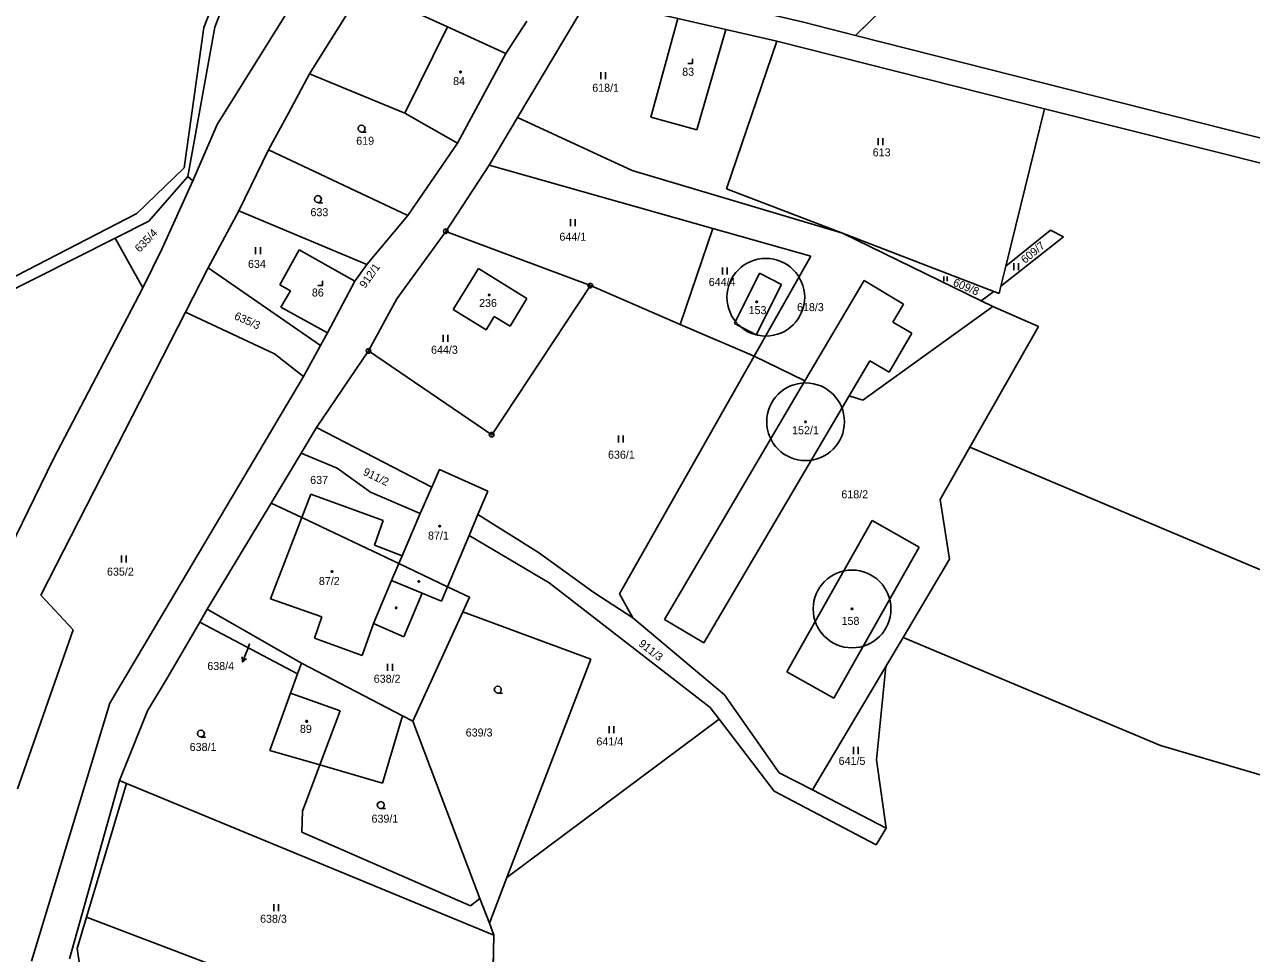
# Model space of a CAD drawing. Extents: x -580551 to -575069, y -1073031 to -1067931.
# Drawn here: x -578344.9 to -578084.3, y -1070721.5 to -1070524.1 of the extents above; entities that cross this region are included whole.
import ezdxf

# ---------------------------------------------------------------- set-up
doc = ezdxf.new("R2010")
doc.units = 0
for name, color, linetype in [('Druh pozemku', 7, 'Continuous'), ('Geodetické body', 7, 'Continuous'), ('Katastrální hranice', 7, 'Continuous'), ('Parcela', 7, 'Continuous'), ('Parcelní číslo', 7, 'Continuous'), ('Parcelní číslo_stavba', 7, 'Continuous'), ('Pomocná vrstva', 7, 'Continuous'), ('SR - hranice státu', 7, 'Continuous'), ('stavební parcely', 7, 'Continuous'), ('Vnitřní kresba', 7, 'Continuous'), ('Vrstva 6', 7, 'Continuous')]:
    doc.layers.add(name, color=color, linetype=linetype)

msp = doc.modelspace()

# ---------------------------------------------------------------- linework, layer by layer
at = {"layer": 'Druh pozemku'}
for p, q in [((-578222.49, -1070534.2), (-578222.49, -1070535.7)), ((-578221.49, -1070535.7), (-578221.49, -1070534.2)), ((-578163.6, -1070548.24), (-578163.6, -1070549.74)), ((-578162.6, -1070549.74), (-578162.6, -1070548.24)), ((-578228.97, -1070565.44), (-578228.97, -1070566.94)), ((-578227.97, -1070566.94), (-578227.97, -1070565.44)), ((-578295.84, -1070571.39), (-578295.84, -1070572.89)), ((-578294.84, -1070572.89), (-578294.84, -1070571.39)), ((-578196.63, -1070575.72), (-578196.63, -1070577.22)), ((-578195.63, -1070577.22), (-578195.63, -1070575.72)), ((-578134.79, -1070574.83), (-578134.79, -1070576.33)), ((-578133.79, -1070576.33), (-578133.79, -1070574.83)), ((-578149.625, -1070577.655), (-578149.625, -1070578.66)), ((-578148.955, -1070578.66), (-578148.955, -1070577.655)), ((-578256.01, -1070590.05), (-578256.01, -1070591.55)), ((-578255.01, -1070591.55), (-578255.01, -1070590.05)), ((-578218.76, -1070611.41), (-578218.76, -1070612.91)), ((-578217.76, -1070612.91), (-578217.76, -1070611.41)), ((-578324.34, -1070636.9), (-578324.34, -1070638.4)), ((-578323.34, -1070638.4), (-578323.34, -1070636.9)), ((-578267.79, -1070659.94), (-578267.79, -1070661.44)), ((-578266.79, -1070661.44), (-578266.79, -1070659.94)), ((-578220.74, -1070673.15), (-578220.74, -1070674.65)), ((-578219.74, -1070674.65), (-578219.74, -1070673.15)), ((-578168.82, -1070677.59), (-578168.82, -1070679.09)), ((-578167.82, -1070679.09), (-578167.82, -1070677.59)), ((-578291.97, -1070710.98), (-578291.97, -1070712.48)), ((-578290.97, -1070712.48), (-578290.97, -1070710.98))]:
    msp.add_line(p, q, dxfattribs=at)
for points in [[(-578204.03, -1070532.41), (-578203.03, -1070532.41), (-578203.03, -1070531.41)], [(-578273.33, -1070546.96), (-578273.71, -1070546.86), (-578273.98, -1070546.59), (-578274.08, -1070546.22), (-578273.98, -1070545.85), (-578273.71, -1070545.58), (-578273.34, -1070545.48), (-578272.97, -1070545.58), (-578272.7, -1070545.85), (-578272.6, -1070546.23), (-578272.7, -1070546.61), (-578272.97, -1070546.88), (-578273.35, -1070546.98), (-578272.35, -1070546.98)], [(-578282.59, -1070561.95), (-578282.97, -1070561.85), (-578283.24, -1070561.58), (-578283.34, -1070561.21), (-578283.24, -1070560.84), (-578282.97, -1070560.57), (-578282.6, -1070560.47), (-578282.23, -1070560.57), (-578281.96, -1070560.84), (-578281.86, -1070561.22), (-578281.96, -1070561.6), (-578282.23, -1070561.87), (-578282.61, -1070561.97), (-578281.61, -1070561.97)], [(-578282.63, -1070579.53), (-578281.63, -1070579.53), (-578281.63, -1070578.53)], [(-578244.38, -1070666.14), (-578244.76, -1070666.04), (-578245.03, -1070665.77), (-578245.13, -1070665.4), (-578245.03, -1070665.03), (-578244.76, -1070664.76), (-578244.39, -1070664.66), (-578244.02, -1070664.76), (-578243.75, -1070665.03), (-578243.65, -1070665.41), (-578243.75, -1070665.79), (-578244.02, -1070666.06), (-578244.4, -1070666.16), (-578243.4, -1070666.16)], [(-578307.46, -1070675.47), (-578307.84, -1070675.37), (-578308.11, -1070675.1), (-578308.21, -1070674.73), (-578308.11, -1070674.36), (-578307.84, -1070674.09), (-578307.47, -1070673.99), (-578307.1, -1070674.09), (-578306.83, -1070674.36), (-578306.73, -1070674.74), (-578306.83, -1070675.12), (-578307.1, -1070675.39), (-578307.48, -1070675.49), (-578306.48, -1070675.49)], [(-578269.24, -1070690.67), (-578269.62, -1070690.57), (-578269.89, -1070690.3), (-578269.99, -1070689.93), (-578269.89, -1070689.56), (-578269.62, -1070689.29), (-578269.25, -1070689.19), (-578268.88, -1070689.29), (-578268.61, -1070689.56), (-578268.51, -1070689.94), (-578268.61, -1070690.32), (-578268.88, -1070690.59), (-578269.26, -1070690.69), (-578268.26, -1070690.69)]]:
    msp.add_lwpolyline(points, dxfattribs=at)
for points in [[(-578252.21, -1070534.05), (-578252.12, -1070534.2), (-578252.21, -1070534.35), (-578252.39, -1070534.35), (-578252.48, -1070534.2), (-578252.39, -1070534.05)], [(-578246.14, -1070581.41), (-578246.05, -1070581.56), (-578246.14, -1070581.71), (-578246.32, -1070581.71), (-578246.41, -1070581.56), (-578246.32, -1070581.41)], [(-578189.29, -1070582.89), (-578189.2, -1070583.04), (-578189.29, -1070583.19), (-578189.47, -1070583.19), (-578189.56, -1070583.04), (-578189.47, -1070582.89)], [(-578178.92, -1070608.36), (-578178.83, -1070608.51), (-578178.92, -1070608.66), (-578179.1, -1070608.66), (-578179.19, -1070608.51), (-578179.1, -1070608.36)], [(-578256.64, -1070630.51), (-578256.55, -1070630.66), (-578256.64, -1070630.81), (-578256.82, -1070630.81), (-578256.91, -1070630.66), (-578256.82, -1070630.51)], [(-578279.53, -1070640.17), (-578279.44, -1070640.32), (-578279.53, -1070640.47), (-578279.71, -1070640.47), (-578279.8, -1070640.32), (-578279.71, -1070640.17)], [(-578261.09, -1070642.28), (-578261, -1070642.43), (-578261.09, -1070642.58), (-578261.27, -1070642.58), (-578261.36, -1070642.43), (-578261.27, -1070642.28)], [(-578265.88, -1070647.89), (-578265.79, -1070648.04), (-578265.88, -1070648.19), (-578266.06, -1070648.19), (-578266.15, -1070648.04), (-578266.06, -1070647.89)], [(-578169.04, -1070648.12), (-578168.95, -1070648.27), (-578169.04, -1070648.42), (-578169.22, -1070648.42), (-578169.31, -1070648.27), (-578169.22, -1070648.12)], [(-578284.89, -1070671.99), (-578284.8, -1070672.14), (-578284.89, -1070672.29), (-578285.07, -1070672.29), (-578285.16, -1070672.14), (-578285.07, -1070671.99)]]:
    msp.add_lwpolyline(points, close=True, dxfattribs=at)
at = {"layer": 'Geodetické body'}
for p, q in [((-578255.57, -1070568.05), (-578255.33, -1070568.05)), ((-578224.84, -1070579.59), (-578224.6, -1070579.59)), ((-578271.97, -1070593.46), (-578271.73, -1070593.46)), ((-578245.81, -1070611.28), (-578245.57, -1070611.28))]:
    msp.add_line(p, q, dxfattribs=at)
for points in [[(-578255.3, -1070567.57), (-578255.05, -1070567.75), (-578254.95, -1070568.04), (-578255.05, -1070568.33), (-578255.3, -1070568.51), (-578255.61, -1070568.51), (-578255.86, -1070568.33), (-578255.96, -1070568.04), (-578255.86, -1070567.75), (-578255.61, -1070567.57)], [(-578224.57, -1070579.11), (-578224.32, -1070579.29), (-578224.22, -1070579.58), (-578224.32, -1070579.87), (-578224.57, -1070580.05), (-578224.88, -1070580.05), (-578225.13, -1070579.87), (-578225.23, -1070579.58), (-578225.13, -1070579.29), (-578224.88, -1070579.11)], [(-578271.7, -1070592.98), (-578271.45, -1070593.16), (-578271.35, -1070593.45), (-578271.45, -1070593.74), (-578271.7, -1070593.92), (-578272.01, -1070593.92), (-578272.26, -1070593.74), (-578272.36, -1070593.45), (-578272.26, -1070593.16), (-578272.01, -1070592.98)], [(-578245.54, -1070610.8), (-578245.29, -1070610.98), (-578245.19, -1070611.27), (-578245.29, -1070611.56), (-578245.54, -1070611.74), (-578245.85, -1070611.74), (-578246.1, -1070611.56), (-578246.2, -1070611.27), (-578246.1, -1070610.98), (-578245.85, -1070610.8)]]:
    msp.add_lwpolyline(points, close=True, dxfattribs=at)
at = {"layer": 'Katastrální hranice'}
for p, q in [((-578306.85, -1070524.72), (-578294.73, -1070494.02)), ((-578311.04, -1070554.58), (-578306.85, -1070524.72)), ((-578321.11, -1070564.23), (-578311.04, -1070554.58)), ((-578356.67, -1070582.67), (-578321.11, -1070564.23))]:
    msp.add_line(p, q, dxfattribs=at)
at = {"layer": 'Parcela'}
for p, q in [((-578168.38, -1070526.44), (-578127.99, -1070486.75)), ((-578294.71, -1070498.96), (-578304.49, -1070524.64)), ((-578282.8, -1070511.36), (-578304.04, -1070545.35)), ((-578284.43, -1070534.61), (-578272.99, -1070516.43)), ((-578225.1, -1070518.49), (-578240.19, -1070543.87)), ((-578238.22, -1070523.39), (-578242.66, -1070530.27)), ((-578206.11, -1070522.84), (-578211.9, -1070543.82)), ((-578206.11, -1070522.84), (-578195.97, -1070525.17)), ((-578168.38, -1070526.44), (-578179.44, -1070523.64)), ((-578304.49, -1070524.64), (-578310.24, -1070556.41)), ((-578202.12, -1070546.5), (-578195.97, -1070525.17)), ((-578195.97, -1070525.17), (-578185.13, -1070527.66)), ((-578066.89, -1070552.12), (-578168.38, -1070526.44)), ((-578195.79, -1070559), (-578185.13, -1070527.66)), ((-578185.13, -1070527.66), (-578128.28, -1070541.99)), ((-578242.66, -1070530.27), (-578252.96, -1070549.32)), ((-578288.87, -1070542.92), (-578284.43, -1070534.61)), ((-578284.43, -1070534.61), (-578264.17, -1070542.91)), ((-578128.28, -1070541.99), (-578136.48, -1070575.43)), ((-578128.28, -1070541.99), (-578025.83, -1070567.81)), ((-578293.14, -1070550.73), (-578288.87, -1070542.92)), ((-578264.17, -1070542.91), (-578252.96, -1070549.32)), ((-578240.19, -1070543.87), (-578246.21, -1070553.99)), ((-578215.82, -1070555.15), (-578240.19, -1070543.87)), ((-578211.9, -1070543.82), (-578202.12, -1070546.5)), ((-578304.04, -1070545.35), (-578309.19, -1070557.3)), ((-578252.96, -1070549.32), (-578263.54, -1070564.7)), ((-578299.44, -1070563.69), (-578293.14, -1070550.73)), ((-578293.14, -1070550.73), (-578263.54, -1070564.7)), ((-578246.21, -1070553.99), (-578255.45, -1070568.05)), ((-578246.21, -1070553.99), (-578198.68, -1070567.45)), ((-578310.24, -1070556.41), (-578318.55, -1070565.89)), ((-578309.19, -1070557.3), (-578315.73, -1070571.66)), ((-578310.24, -1070556.41), (-578309.19, -1070557.3)), ((-578171.15, -1070568.45), (-578215.82, -1070555.15)), ((-578171.15, -1070568.45), (-578195.79, -1070559)), ((-578305.9, -1070575.83), (-578299.44, -1070563.69)), ((-578272.24, -1070575.1), (-578299.44, -1070563.69)), ((-578263.54, -1070564.7), (-578272.24, -1070575.1)), ((-578318.55, -1070565.89), (-578325.66, -1070569.48)), ((-578255.45, -1070568.05), (-578265.82, -1070582.39)), ((-578224.72, -1070579.59), (-578255.45, -1070568.05)), ((-578198.68, -1070567.45), (-578177.87, -1070573.34)), ((-578325.66, -1070569.48), (-578383.01, -1070598.43)), ((-578325.66, -1070569.48), (-578319.77, -1070580.02)), ((-578171.15, -1070568.45), (-578139.01, -1070580.82)), ((-578171.15, -1070568.45), (-578141.7, -1070582.84)), ((-578315.73, -1070571.66), (-578319.77, -1070580.02)), ((-578286.56, -1070572), (-578290.7, -1070579.38)), ((-578274.76, -1070578.65), (-578286.56, -1070572)), ((-578189.92, -1070594.59), (-578177.87, -1070573.34)), ((-578310.76, -1070585.22), (-578305.9, -1070575.83)), ((-578305.9, -1070575.83), (-578282.07, -1070592.28)), ((-578272.24, -1070575.1), (-578274.76, -1070578.65)), ((-578253.88, -1070584.64), (-578248.49, -1070575.93)), ((-578248.49, -1070575.93), (-578238.21, -1070582.34)), ((-578136.48, -1070575.43), (-578137.53, -1070579.7)), ((-578188.77, -1070576.93), (-578194.12, -1070587.66)), ((-578188.77, -1070576.93), (-578184.15, -1070579.31)), ((-578179.15, -1070599.83), (-578166.59, -1070578.47)), ((-578158.2, -1070583.49), (-578166.59, -1070578.47)), ((-578319.77, -1070580.02), (-578338.75, -1070616.37)), ((-578290.7, -1070579.38), (-578288.43, -1070580.7)), ((-578288.43, -1070580.7), (-578290.47, -1070584.17)), ((-578274.76, -1070578.65), (-578280.6, -1070589.58)), ((-578245.69, -1070611.28), (-578224.72, -1070579.59)), ((-578184.15, -1070579.31), (-578189.5, -1070590.04)), ((-578139.01, -1070580.82), (-578137.91, -1070581.24)), ((-578137.53, -1070579.7), (-578137.91, -1070581.24)), ((-578265.82, -1070582.39), (-578271.85, -1070593.46)), ((-578238.21, -1070582.34), (-578241.79, -1070588.19)), ((-578160.48, -1070587.34), (-578158.2, -1070583.49)), ((-578141.7, -1070582.84), (-578139.25, -1070584.04)), ((-578341.49, -1070645.34), (-578310.76, -1070585.22)), ((-578310.76, -1070585.22), (-578291.81, -1070594.05)), ((-578290.47, -1070584.17), (-578280.6, -1070589.58)), ((-578246.85, -1070588.94), (-578253.88, -1070584.64)), ((-578245.14, -1070586.14), (-578246.85, -1070588.94)), ((-578241.79, -1070588.19), (-578245.14, -1070586.14)), ((-578166.87, -1070603.91), (-578139.25, -1070584.04)), ((-578139.25, -1070584.04), (-578129.53, -1070588.29)), ((-578189.5, -1070590.04), (-578194.12, -1070587.66)), ((-578156.42, -1070589.71), (-578160.48, -1070587.34)), ((-578129.53, -1070588.29), (-578144.08, -1070613.9)), ((-578280.6, -1070589.58), (-578282.07, -1070592.28)), ((-578161.26, -1070597.95), (-578156.42, -1070589.71)), ((-578291.81, -1070594.05), (-578285.66, -1070598.89)), ((-578282.07, -1070592.28), (-578285.66, -1070598.89)), ((-578271.85, -1070593.46), (-578282.88, -1070609.74)), ((-578271.85, -1070593.46), (-578245.69, -1070611.28)), ((-578218.55, -1070645.08), (-578189.92, -1070594.59)), ((-578179.15, -1070599.83), (-578189.92, -1070594.59)), ((-578165.36, -1070595.54), (-578169.72, -1070602.96)), ((-578165.36, -1070595.54), (-578161.26, -1070597.95)), ((-578285.66, -1070598.89), (-578326.82, -1070668.32)), ((-578208.98, -1070650.52), (-578179.15, -1070599.83)), ((-578169.72, -1070602.96), (-578200.59, -1070655.47)), ((-578169.72, -1070602.96), (-578166.87, -1070603.91)), ((-578282.88, -1070609.74), (-578286.15, -1070615.17)), ((-578282.88, -1070609.74), (-578258.44, -1070622.43)), ((-578144.08, -1070613.9), (-578150.39, -1070625.01)), ((-578034.23, -1070660.29), (-578144.08, -1070613.9)), ((-578338.75, -1070616.37), (-578366.44, -1070672.97)), ((-578286.15, -1070615.17), (-578292.53, -1070625.77)), ((-578278.53, -1070618.35), (-578286.15, -1070615.17)), ((-578271.46, -1070623.46), (-578278.53, -1070618.35)), ((-578256.81, -1070618.66), (-578258.44, -1070622.43)), ((-578246.51, -1070623.24), (-578256.81, -1070618.66)), ((-578258.44, -1070622.43), (-578260.86, -1070628.01)), ((-578286.02, -1070628.86), (-578284.11, -1070623.85)), ((-578284.11, -1070623.85), (-578268.78, -1070629.48)), ((-578260.86, -1070628.01), (-578271.46, -1070623.46)), ((-578246.51, -1070623.24), (-578248.61, -1070628.21)), ((-578150.39, -1070625.01), (-578148.4, -1070637.69)), ((-578292.53, -1070625.77), (-578306.15, -1070648.33)), ((-578286.02, -1070628.86), (-578292.53, -1070625.77)), ((-578260.86, -1070628.01), (-578264.74, -1070636.97)), ((-578292.65, -1070646.11), (-578286.02, -1070628.86)), ((-578265.45, -1070638.62), (-578286.02, -1070628.86)), ((-578268.78, -1070629.48), (-578270.57, -1070634.71)), ((-578248.61, -1070628.21), (-578250.5, -1070632.69)), ((-578235.78, -1070636.28), (-578248.61, -1070628.21)), ((-578183, -1070661.61), (-578164.84, -1070629.48)), ((-578164.84, -1070629.48), (-578154.89, -1070635.11)), ((-578250.5, -1070632.69), (-578255.07, -1070643.54)), ((-578233.47, -1070642.7), (-578250.5, -1070632.69)), ((-578270.57, -1070634.71), (-578264.74, -1070636.97)), ((-578154.89, -1070635.11), (-578173.03, -1070667.24)), ((-578223.97, -1070644.79), (-578235.78, -1070636.28)), ((-578148.4, -1070637.69), (-578158.3, -1070654.34)), ((-578255.07, -1070643.54), (-578265.45, -1070638.62)), ((-578255.07, -1070643.54), (-578256.37, -1070646.61)), ((-578250.37, -1070645.77), (-578255.07, -1070643.54)), ((-578199.25, -1070669.19), (-578233.47, -1070642.7)), ((-578334.57, -1070652.72), (-578341.49, -1070645.34)), ((-578281.76, -1070649.93), (-578292.65, -1070646.11)), ((-578264.33, -1070654.17), (-578260.48, -1070644.91)), ((-578256.37, -1070646.61), (-578260.48, -1070644.91)), ((-578251.81, -1070648.91), (-578250.37, -1070645.77)), ((-578215.72, -1070650.18), (-578223.97, -1070644.79)), ((-578215.72, -1070650.18), (-578218.55, -1070645.08)), ((-578306.15, -1070648.33), (-578307.72, -1070651.05)), ((-578286.12, -1070659.78), (-578306.15, -1070648.33)), ((-578262.46, -1070672.1), (-578251.81, -1070648.91)), ((-578224.63, -1070658.91), (-578251.81, -1070648.91)), ((-578307.72, -1070651.05), (-578314.4, -1070662.62)), ((-578286.94, -1070662.05), (-578307.72, -1070651.05)), ((-578283.36, -1070654.46), (-578281.76, -1070649.93)), ((-578270.81, -1070651.39), (-578273.24, -1070658.16)), ((-578270.81, -1070651.39), (-578264.33, -1070654.17)), ((-578196.21, -1070666.55), (-578215.72, -1070650.18)), ((-578200.59, -1070655.47), (-578208.98, -1070650.52)), ((-578346.44, -1070686.49), (-578334.57, -1070652.72)), ((-578273.24, -1070658.16), (-578283.36, -1070654.46)), ((-578158.3, -1070654.34), (-578161.98, -1070660.53)), ((-578103.62, -1070677.27), (-578158.3, -1070654.34)), ((-578242.46, -1070705.32), (-578224.63, -1070658.91)), ((-578286.94, -1070662.05), (-578286.12, -1070659.78)), ((-578264.61, -1070671), (-578286.12, -1070659.78)), ((-578173.03, -1070667.24), (-578183, -1070661.61)), ((-578161.98, -1070660.53), (-578177.55, -1070686.72)), ((-578314.4, -1070662.62), (-578318.82, -1070669.89)), ((-578288.41, -1070666.14), (-578286.94, -1070662.05)), ((-578292.8, -1070678.34), (-578288.41, -1070666.14)), ((-578184.62, -1070683.06), (-578196.21, -1070666.55)), ((-578326.82, -1070668.32), (-578343.43, -1070723.09)), ((-578197.37, -1070671.66), (-578199.25, -1070669.19)), ((-578318.82, -1070669.89), (-578324.79, -1070684.74)), ((-578268.86, -1070685.27), (-578264.61, -1070671)), ((-578262.46, -1070672.1), (-578264.61, -1070671)), ((-578248.18, -1070709.76), (-578262.46, -1070672.1)), ((-578197.37, -1070671.66), (-578185.69, -1070686.96)), ((-578069.14, -1070687.4), (-578103.62, -1070677.27)), ((-578292.8, -1070678.34), (-578282.19, -1070681.41)), ((-578285.88, -1070691.23), (-578282.19, -1070681.41)), ((-578282.19, -1070681.41), (-578268.86, -1070685.27)), ((-578324.79, -1070684.74), (-578335.36, -1070722.61)), ((-578331.78, -1070713.77), (-578323.28, -1070685.38)), ((-578323.28, -1070685.38), (-578324.79, -1070684.74)), ((-578323.28, -1070685.38), (-578245.22, -1070717.56)), ((-578177.55, -1070686.72), (-578184.62, -1070683.06)), ((-578185.69, -1070686.96), (-578164.04, -1070698.41)), ((-578161.88, -1070694.82), (-578177.55, -1070686.72)), ((-578286, -1070695.7), (-578285.88, -1070691.23)), ((-578250.22, -1070711.31), (-578286, -1070695.7)), ((-578164.04, -1070698.41), (-578161.88, -1070694.82)), ((-578246.19, -1070715.01), (-578242.46, -1070705.32)), ((-578248.18, -1070709.76), (-578250.22, -1070711.31)), ((-578246.19, -1070715.01), (-578248.18, -1070709.76)), ((-578333.76, -1070720.41), (-578331.78, -1070713.77)), ((-578331.78, -1070713.77), (-578283.24, -1070732.18)), ((-578245.22, -1070717.56), (-578246.19, -1070715.01)), ((-578245.22, -1070717.56), (-578245.81, -1070746.37)), ((-578333.76, -1070720.41), (-578333.03, -1070725.08))]:
    msp.add_line(p, q, dxfattribs=at)
at = {"layer": 'Pomocná vrstva'}
for p in [(-578298.614, -1070659.537), (-578297.11, -1070655.67)]:
    msp.add_line(p, (-578297.53, -1070656.74), dxfattribs=at)
msp.add_lwpolyline([(-578297.786, -1070658.786), (-578298.614, -1070659.537), (-578298.719, -1070658.424)], dxfattribs=at)
at = {"layer": 'SR - hranice státu'}
for p, q in [((-578195.79, -1070559), (-578185.13, -1070527.66)), ((-578171.15, -1070568.45), (-578195.79, -1070559))]:
    msp.add_line(p, q, dxfattribs=at)
for points in [[(-578185.13, -1070527.66), (-578195.97, -1070525.17), (-578206.11, -1070522.84), (-578225.1, -1070518.49), (-578222.3, -1070513.55), (-578179.44, -1070523.64), (-578168.38, -1070526.44), (-578127.99, -1070486.75)], [(-578246.21, -1070553.99), (-578240.19, -1070543.87), (-578215.82, -1070555.15), (-578171.15, -1070568.45)], [(-578245.69, -1070611.28), (-578224.72, -1070579.59), (-578255.45, -1070568.05), (-578246.21, -1070553.99)], [(-578246.51, -1070623.24), (-578256.81, -1070618.66), (-578258.44, -1070622.43), (-578282.88, -1070609.74), (-578271.85, -1070593.46), (-578245.69, -1070611.28)], [(-578224.63, -1070658.91), (-578251.81, -1070648.91), (-578250.37, -1070645.77), (-578255.07, -1070643.54), (-578250.5, -1070632.69), (-578248.61, -1070628.21), (-578246.51, -1070623.24)], [(-578245.81, -1070746.37), (-578245.22, -1070717.56), (-578246.19, -1070715.01), (-578242.46, -1070705.32), (-578224.63, -1070658.91)]]:
    msp.add_lwpolyline(points, dxfattribs=at)
at = {"layer": 'stavební parcely'}
for centre in [(-578187.45, -1070582.041), (-578179.01, -1070608.51), (-578169.13, -1070648.27)]:
    msp.add_circle(centre, 8.257, dxfattribs=at)
at = {"layer": 'Vnitřní kresba'}
for p, q in [((-578272.99, -1070516.43), (-578255.06, -1070524.59)), ((-578264.17, -1070542.91), (-578255.06, -1070524.59)), ((-578255.06, -1070524.59), (-578242.66, -1070530.27)), ((-578265.45, -1070638.62), (-578264.74, -1070636.97)), ((-578265.45, -1070638.62), (-578267.01, -1070642.21)), ((-578270.81, -1070651.39), (-578267.01, -1070642.21)), ((-578267.01, -1070642.21), (-578260.48, -1070644.91)), ((-578288.41, -1070666.14), (-578277.86, -1070669.9)), ((-578282.19, -1070681.41), (-578277.86, -1070669.9))]:
    msp.add_line(p, q, dxfattribs=at)
at = {"layer": 'Vrstva 6'}
for p, q in [((-578198.68, -1070567.45), (-578205.67, -1070587.81)), ((-578136.48, -1070575.43), (-578126.97, -1070567.81)), ((-578126.97, -1070567.81), (-578124.24, -1070569.22)), ((-578124.24, -1070569.22), (-578137.53, -1070579.7)), ((-578205.67, -1070587.81), (-578224.72, -1070579.59)), ((-578139.01, -1070580.82), (-578141.7, -1070582.84)), ((-578189.92, -1070594.59), (-578205.67, -1070587.81)), ((-578163.92, -1070680.33), (-578161.98, -1070660.53)), ((-578197.37, -1070671.66), (-578242.46, -1070705.32)), ((-578161.88, -1070694.82), (-578163.92, -1070680.33))]:
    msp.add_line(p, q, dxfattribs=at)

# ---------------------------------------------------------------- texts
at = {"layer": 'Parcelní číslo'}
for s, height, p in [('618/1', 1.7, (-578224.329, -1070538.39)), ('619', 1.7, (-578274.467, -1070549.65)), ('613', 1.7, (-578164.744, -1070552.12)), ('633', 1.7, (-578284.188, -1070564.83)), ('644/1', 1.7, (-578231.302, -1070570.04)), ('634', 1.7, (-578297.461, -1070575.82)), ('644/4', 1.7, (-578199.579, -1070579.65)), ('618/3', 1.7, (-578180.823, -1070585)), ('644/3', 1.7, (-578258.576, -1070594.06)), ('636/1', 1.7, (-578220.979, -1070616.35)), ('637', 1.7, (-578284.246, -1070621.71)), ('618/2', 1.7, (-578171.401, -1070624.76)), ('635/2', 1.7, (-578327.412, -1070641.19)), ('638/4', 0.1, (-578297.319, -1070655.67)), ('638/2', 1.7, (-578270.745, -1070663.95)), ('639/3', 1.7, (-578251.203, -1070675.37)), ('638/1', 1.7, (-578309.853, -1070678.45)), ('641/4', 1.7, (-578223.442, -1070677.27)), ('641/5', 1.7, (-578171.984, -1070681.4)), ('639/1', 1.7, (-578271.219, -1070693.67)), ('638/3', 1.7, (-578294.896, -1070714.94))]:
    msp.add_text(s, height=height, dxfattribs=at).set_placement(p)
for s, rotation, p in [('635/4', 46.23769, (-578320.477, -1070572.643)), ('609/7', 39.24761, (-578132.397, -1070574.989)), ('912/1', 54.83206, (-578272.558, -1070580.267)), ('609/8', 337.12837, (-578147.829, -1070579.517)), ('635/3', 335.86786, (-578300.532, -1070586.622)), ('911/2', 334.20628, (-578273.173, -1070619.721)), ('911/3', 322.00228, (-578214.624, -1070655.946))]:
    msp.add_text(s, height=1.7, rotation=rotation, dxfattribs=at).set_placement(p)
at = {"layer": 'Parcelní číslo_stavba'}
for s, p in [('83', (-578205.216, -1070535)), ('84', (-578253.89, -1070536.97)), ('86', (-578283.89, -1070581.89)), ('236', (-578248.376, -1070584.12)), ('153', (-578191.115, -1070585.64)), ('152/1', (-578181.871, -1070611.15)), ('87/1', (-578259.222, -1070633.53)), ('87/2', (-578282.404, -1070643.19)), ('158', (-578171.366, -1070651.65)), ('89', (-578286.43, -1070674.6))]:
    msp.add_text(s, height=1.7, dxfattribs=at).set_placement(p)
at = {"layer": 'Pomocná vrstva'}
msp.add_text('638/4', height=1.7, dxfattribs=at).set_placement((-578306.107, -1070661.24))

doc.saveas('drawing.dxf')
